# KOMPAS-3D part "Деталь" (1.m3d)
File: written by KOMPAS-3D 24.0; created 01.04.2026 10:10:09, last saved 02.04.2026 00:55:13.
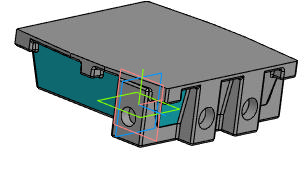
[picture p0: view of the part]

Document properties: Автор: R2D2; Полное имя файла: E:\Работа\Зайцев\Аксессуары для пневмоприводов\Блок концевых выключателей DN.ru\APL-410N EX Блок концевых выключателей DN.ru\исходные материалы\1.m3d

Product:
- Part/product: Деталь
    Масса: 10.195283

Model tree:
1. Эскиз:1
2. Элемент выдавливания:1
     Расстояние 1 = 8
3. Эскиз:2
4. Элемент выдавливания:2
     Расстояние 1 = 8
5. Уклон:1  (with: Грань.Элемент выдавливания:1)
     Угол уклона = 15
6. Уклон:3  (with: Грань.Элемент выдавливания:2)
     Угол уклона = 15
7. Массив по концентрической сетке:1  (2 pattern instances)
8. Тело 2  (2 pattern instances)
     N 1 = 1; Шаг 1 = 10; Шаг 2 = 360; Номер 1 = 1
9. Эскиз:3  (with: Грань.Элемент выдавливания:1)
10. Элемент выдавливания:3
     Расстояние 1 = 50
11. Эскиз:7  (with: Грань.Элемент выдавливания:3, Ребро.Элемент выдавливания:2)  (labels: Ребро.Тело 2.Экземпляр ( 1, 3 ))
12. Элемент выдавливания:6  (with: Грань.Элемент выдавливания:2, Массив по концентрической сетке:1, Эскиз:7, Грань.Уклон:1)  (4 pattern instances)
     Расстояние 1 = 8; N 1 = 1; Шаг 1 = 10; Шаг 2 = 360; Номер 1 = 1
13. Эскиз:9  (labels: Грань.Тело 2.Экземпляр ( 1, 3 ); Ребро.Тело 2.Экземпляр ( 1, 2 ))
14. Элемент выдавливания:8
     Расстояние 2 = 10
15. Эскиз:10  (labels: Грань.Тело 2.Экземпляр ( 1, 3 ))
16. Элемент выдавливания:9
     Расстояние 1 = 24
17. Эскиз:11  (with: Грань.Элемент выдавливания:9)
18. Элемент выдавливания:10
     Расстояние 1 = 3
19. Эскиз:12  (with: Грань.Элемент выдавливания:10)
20. Элемент выдавливания:11
     Расстояние 2 = 7
21. Фаска:2  (with: Ребро.Элемент выдавливания:10, Ребро.Элемент выдавливания:9)
     Угол = 45; Длина 1 = 0.5; Длина 2 = 0.5
22. Эскиз:13  (labels: Грань.Тело 2.Экземпляр ( 1, 3 ))
23. Элемент выдавливания:12
     Расстояние 1 = 1
24. Массив по концентрической сетке:3  (with: Элемент выдавливания:8, Эскиз:9, Грань.Уклон:1)  (4 pattern instances)
     Шаг 2 = 360
25. Уклон:4  (with: Грань.Элемент выдавливания:3)
     Угол уклона = 10
26. Скругление:14  (with: Ребро.Элемент выдавливания:3, Грань.Элемент выдавливания:3)
     Радиус = 3
27. Эскиз:17  (with: Грань.Элемент выдавливания:3, Ребро.Элемент выдавливания:3)
28. Элемент выдавливания:16
     Расстояние 2 = 5
29. Эскиз:18  (with: Грань.Элемент выдавливания:16, Вершина.Элемент выдавливания:16, Ребро.Элемент выдавливания:16)
30. Элемент выдавливания:17
     Расстояние 1 = 10
31. Эскиз:19  (with: Ребро.Элемент выдавливания:16, Ребро.Элемент выдавливания:2)
32. Элемент выдавливания:18
     Расстояние 1 = 178
33. Скругление:20  (with: Ребро.Элемент выдавливания:18, Грань.Элемент выдавливания:16, Грань.Элемент выдавливания:17, Грань.Элемент выдавливания:18, Ребро.Элемент выдавливания:16)
     Радиус = 2
34. Эскиз:20  (with: Грань.Элемент выдавливания:18, Ребро.Скругление:20)
35. Элемент выдавливания:19
     Расстояние 2 = 10
36. Зеркальный массив:4
37. Экземпляр ( 1 )
38. Экземпляр ( 2 )  (with: Элемент выдавливания:19)
39. Эскиз:21  (with: Ребро.Скругление:20)
40. Элемент выдавливания:20  (with: Грань.Элемент выдавливания:16)
     Расстояние 1 = 87.0315
41. Скругление:21  (with: Грань.Элемент выдавливания:20)
     Радиус = 2
42. Эскиз:22  (with: Грань.Элемент выдавливания:16, Ребро.Скругление:21)
43. Элемент выдавливания:21
     Расстояние 2 = 5
44. Эскиз:23  (with: Грань.Элемент выдавливания:18, Ребро.Скругление:20, Ребро.Элемент выдавливания:16)
45. Элемент выдавливания:22  (with: Грань.Элемент выдавливания:16)
     Расстояние 1 = 17.5; Расстояние 2 = 10
46. Скругление:22  (with: Ребро.Элемент выдавливания:22, Грань.Элемент выдавливания:22)
     Радиус = 2
47. Эскиз:24  (with: Грань.Элемент выдавливания:16, Ребро.Скругление:22)
48. Элемент выдавливания:23
     Расстояние 2 = 10

Expressions: v1549/2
